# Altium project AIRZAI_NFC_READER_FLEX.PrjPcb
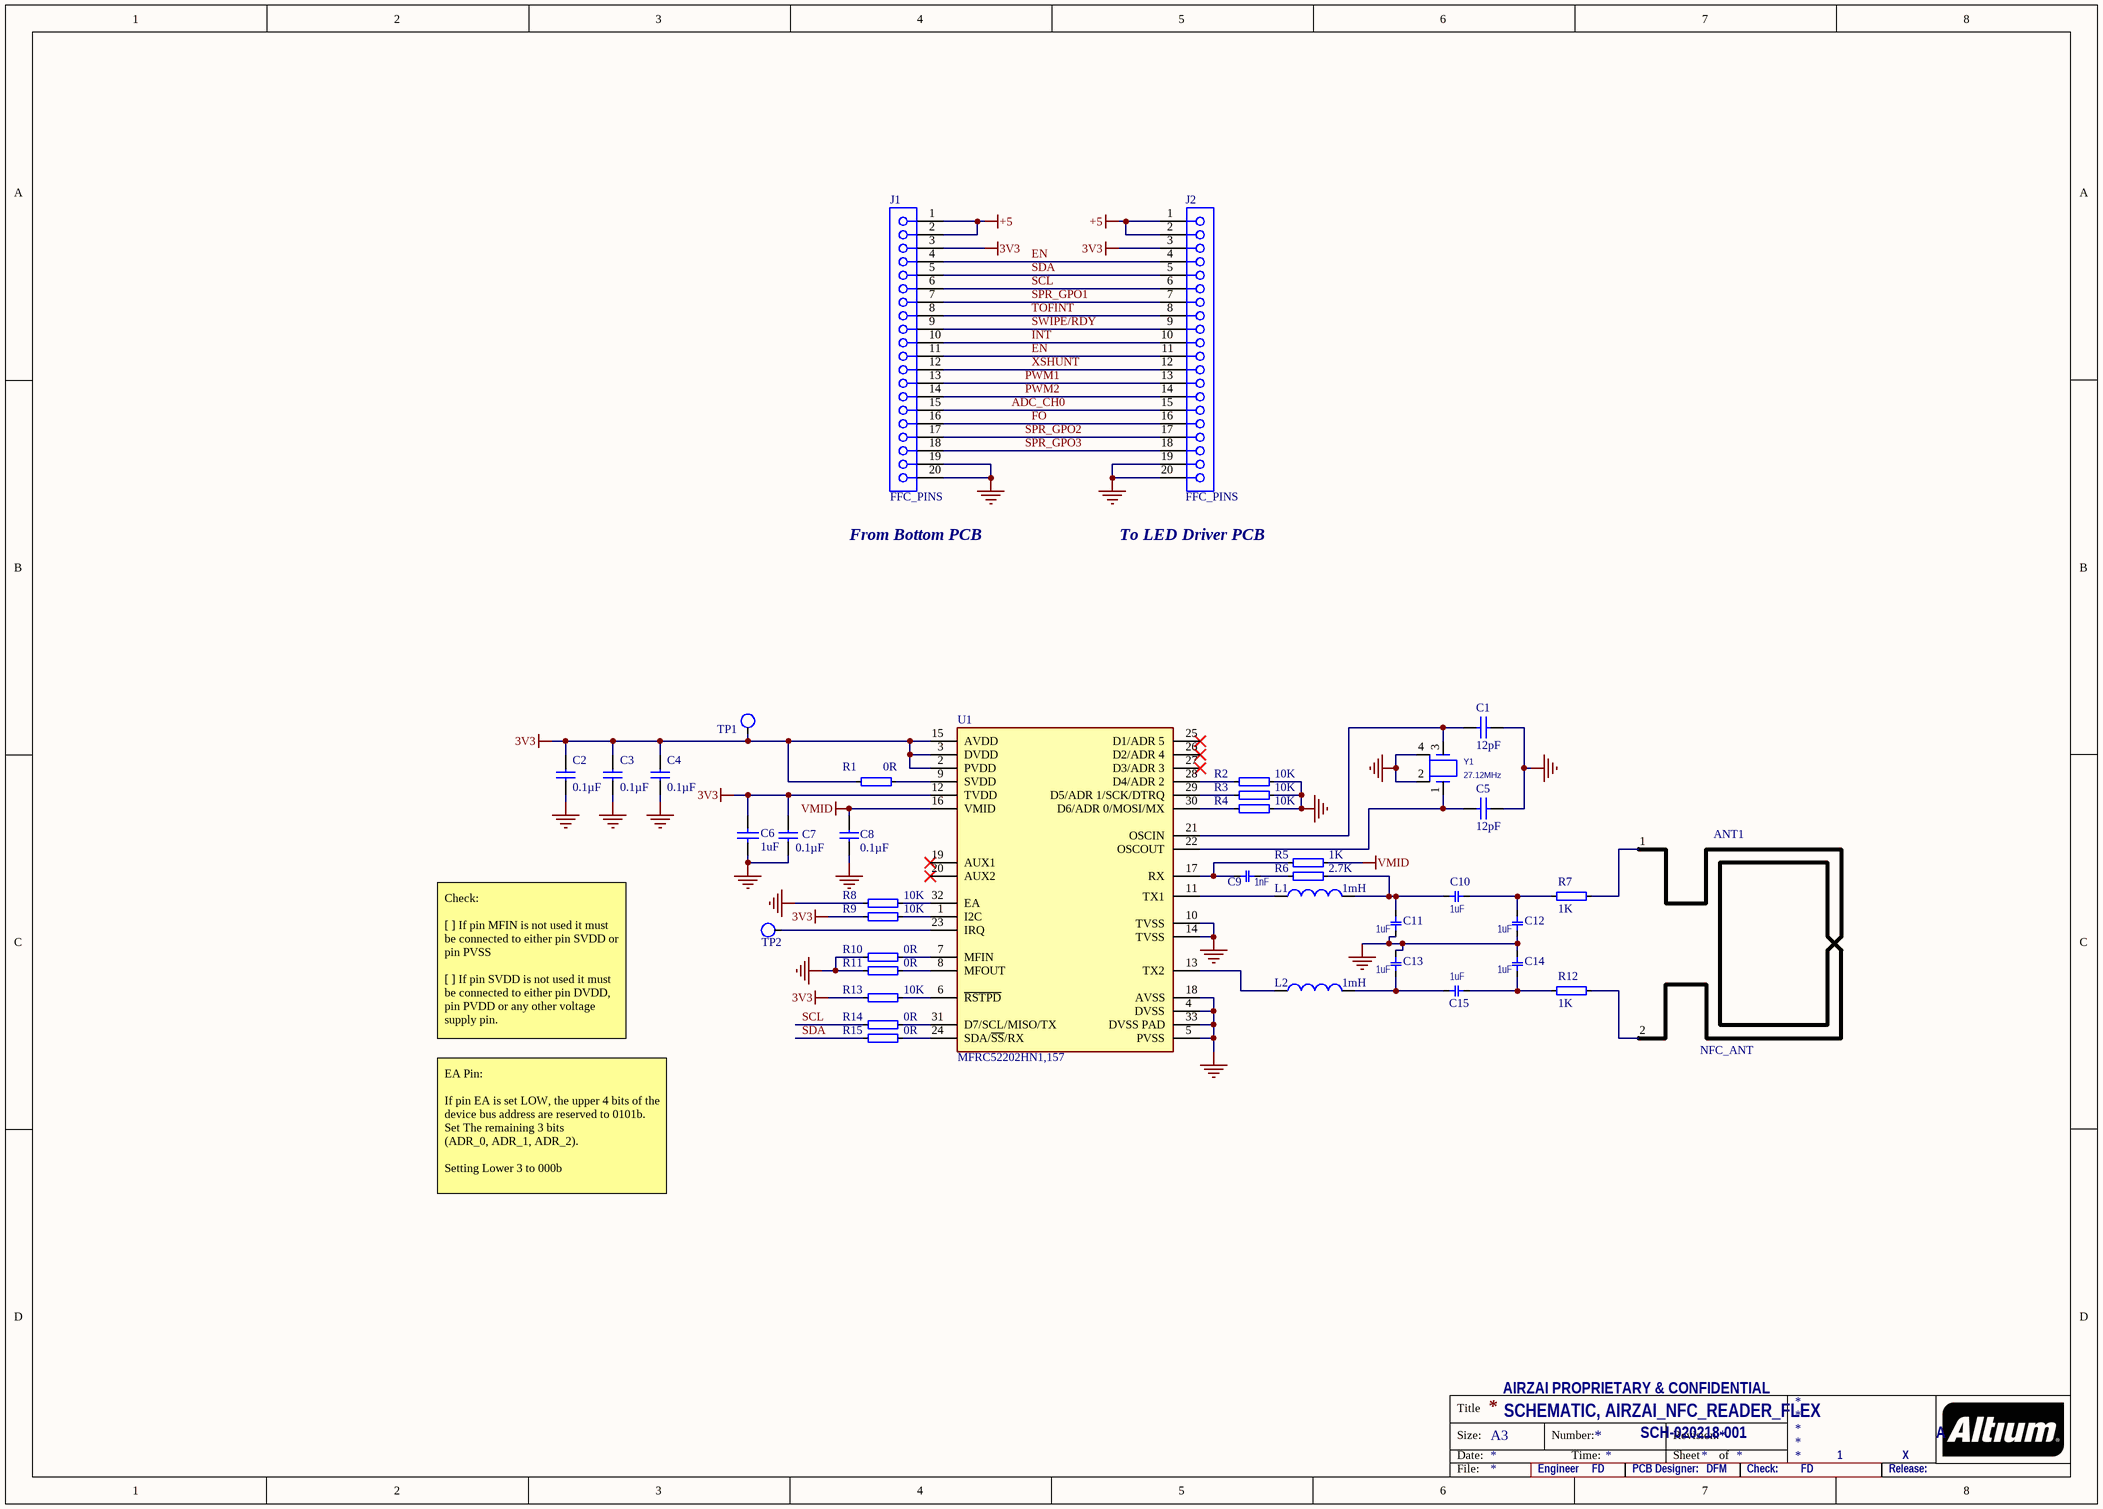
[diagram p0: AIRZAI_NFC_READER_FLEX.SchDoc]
1 sheet, 39 parts. Net scope: global (net labels, ports and power ports of the same name join across sheets).
Board file: AIRZAI_NFC_READER_FLEX.PcbDoc

## Sheet AIRZAI_NFC_READER_FLEX.SchDoc
size A3

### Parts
ANT1  NFC_ANT
C1  12pF
C2  0.1µF  [0402CAP]
C3  0.1µF  [0402CAP]
C4  0.1µF  [0402CAP]
C5  12pF
C6  1uF  [CAPC0402(1005)60_M]
C7  0.1µF  [0402CAP]
C8  0.1µF  [0402CAP]
C9  1nF  [0603]
C10  1uF  [0603]
C11  1uF  [0603]
C12  1uF  [0603]
C13  1uF  [0603]
C14  1uF  [0603]
C15  1uF  [0603]
J1  FFC_PINS
J2  FFC_PINS
L1  1mH  [0402-A]
L2  1mH  [0402-A]
R1  0R  [0402]
R2  10K  [0402]
R3  10K  [0402]
R4  10K  [0402]
R5  1K  [0402]
R6  2.7K  [0402]
R7  1K
R8  10K  [0402]
R9  10K  [0402]
R10  0R  [0402]
R11  0R  [0402]
R12  1K
R13  10K  [0402]
R14  0R  [0402]
R15  0R  [0402]
TP1  WIREPT  [TP_0.9MM]  (value not drawn)
TP2  WIREPT  [TP_0.9MM]  (value not drawn)
U1  Part Number: MFRC52202HN1,157  [NXP_SOT617-1_0]  (hidden comment: MFRC52201HN1,157)
Y1  27.12MHz  [XTAL_2016]

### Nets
3V3: C2.1 C3.1 C4.1 C6.2 C7.1 J1.3 J2.3 R1.2 R9.2 R13.2 TP1.1 U1.2(PVDD) U1.3(DVDD) U1.12(TVDD) U1.15(AVDD)
+5: J1.1 J1.2 J2.1 J2.2
GND: C1.1 C2.2 C3.2 C4.2 C5.1 C6.1 C7.2 C8.2 C11.1 C12.1 C13.2 C14.2 J1.19 J1.20 J2.19 J2.20 R2.1 R3.1 R4.1 R8.2 R10.2 R11.2 U1.4(DVSS) U1.5(PVSS) U1.10(TVSS) U1.14(TVSS) U1.18(AVSS) U1.33(DVSS_PAD) Y1.2 Y1.4
VMID: C8.1 R5.1 U1.16(VMID)
ADC_CH0: J1.15 J2.15
EN: J1.4 J1.11 J2.4 J2.11
FO: J1.16 J2.16
INT: J1.10 J2.10
PWM1: J1.13 J2.13
PWM2: J1.14 J2.14
SCL: J1.6 J2.6 R14.2
SDA: J1.5 J2.5 R15.2
SPR_GPO1: J1.7 J2.7
SPR_GPO2: J1.17 J2.17
SPR_GPO3: J1.18 J2.18
SWIPE/RDY: J1.9 J2.9
TOFINT: J1.8 J2.8
XSHUNT: J1.12 J2.12
NetANT1_1: ANT1.1 R7.1
NetANT1_2: ANT1.2 R12.1
NetC1_2: C1.2 U1.21(OSCIN) Y1.3
NetC5_2: C5.2 U1.22(OSCOUT) Y1.1
NetC9_1: C9.1 R6.2
NetC9_2: C9.2 R5.2 U1.17(RX)
NetC10_1: C10.1 C12.2 R7.2
NetC10_2: C10.2 C11.2 L1.2 R6.1
NetC13_1: C13.1 C15.2 L2.2
NetC14_1: C14.1 C15.1 R12.2
NetL1_1: L1.1 U1.11(TX1)
NetL2_1: L2.1 U1.13(TX2)
NetR1_1: R1.1 U1.9(SVDD)
NetR2_2: R2.2 U1.28(D4/ADR_2)
NetR3_2: R3.2 U1.29(D5/ADR_1/SCK/DTRQ)
NetR4_2: R4.2 U1.30(D6/ADR_0/MOSI/MX)
NetR8_1: R8.1 U1.32(EA)
NetR9_1: R9.1 U1.1(I2C)
NetR10_1: R10.1 U1.7(MFIN)
NetR11_1: R11.1 U1.8(MFOUT)
NetR13_1: R13.1 U1.6(~{RSTPD})
NetR14_1: R14.1 U1.31(D7/SCL/MISO/TX)
NetR15_1: R15.1 U1.24(SDA/~{SS}/RX)
NetTP2_1: TP2.1 U1.23(IRQ)

Not connected (* = marked no-connect by the designer): U1 19(AUX1)* 20(AUX2)* 25(D1/ADR_5)* 26(D2/ADR_4)* 27(D3/ADR_3)*

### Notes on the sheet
- (near J1) From Bottom PCB
- (near J2) To LED Driver PCB
- Check:
  [ ] If pin MFIN is not used it must be connected to either pin SVDD or pin PVSS
  [ ] If pin SVDD is not used it must be connected to either pin DVDD, pin PVDD or any other voltage supply pin.
- EA Pin:
  If pin EA is set LOW, the upper 4 bits of the device bus address are reserved to 0101b. Set The remaining 3 bits
  (ADR_0, ADR_1, ADR_2).
  Setting Lower 3 to 000b
- AIRZAI PROPRIETARY & CONFIDENTIAL
- SCHEMATIC, AIRZAI_NFC_READER_FLEX
- SCH-020218-001
- 1
- X
- A
- Engineer
- FD
- PCB Designer:
- DFM
- Check:
- Release:

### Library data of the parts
C1 C5 = CAP: CAP CER 12PF 50V C0G/NP0 0402; Manufacturer: KEMET; Manufacturer Part Number: C0402C120J5GACTU; Dielectric Material: Ceramic; Tolerance: 5%; Dielectric: C0G; Temperature Coefficient: 30ppm/°C
C2-C4 C7 C8 = C0402-100n: Capacitor, X7R, ±10%; Manufacturer: TDK; Manufacturer Part Number: C1005X7R1C104K; Note: 16V ±10% X7R; Case-EIA: 0402; Case-Metric: 1005; Rated Voltage: 16 V; Tolerance: Â±20%
C6 = CAP: CAP 1uF 16V ±10% 0402 (1005 Metric) Thickness 0.6mm SMD; Manufacturer: Taiyo Yuden; Manufacturer Part Number: EMK105BJ105KV-F; Dielectric: X5R
C9-C15 = 56p
L1 L2 = Inductor
R1 R10 R11 R14 R15 = R0402-12k: Resistor, ±1%, 0.063W; Manufacturer: Panasonic; Manufacturer Part Number: ERJ-2GE0R00X; Note: 0.1W JUMPER; Case-Metric: 1005; Tolerance: ±5%
R2-R4 R8 R9 R13 = R0402-12k: Resistor 10K, ±1%, 0.063W; Manufacturer: Vishay Dale; Manufacturer Part Number: CRCW040210K0JNED; Resistance: 10kR; Power Rating: 63mW; Tolerance: 5%; Voltage Rating: 50V; Temperature Coefficient: 200ppm/°C
R5 R7 R12 = R0402-12k: Resistor 1K, ±1%, 0.063W
R6 = R0402-12k: Resistor 2.7K, ±1%, 0.063W
U1 = MFRC52201HN1,157: IC RFID READER 13.56MHZ 32HVQFN; Manufacturer: NXP; Mfg Package Ident: SOT617-1
Y1 = ZTB_2: CRYSTAL 27.12MHZ 10PF SMD; Manufacturer: ECS International; Manufacturer Part Number: ECS-271.2-10-37-CKM-TR; Description: Crystal 27.12MHz ±10ppm (Tol) ±10ppm (Stability) 10pF FUND 60Ohm 4-Pin Mini-CSMD T/R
